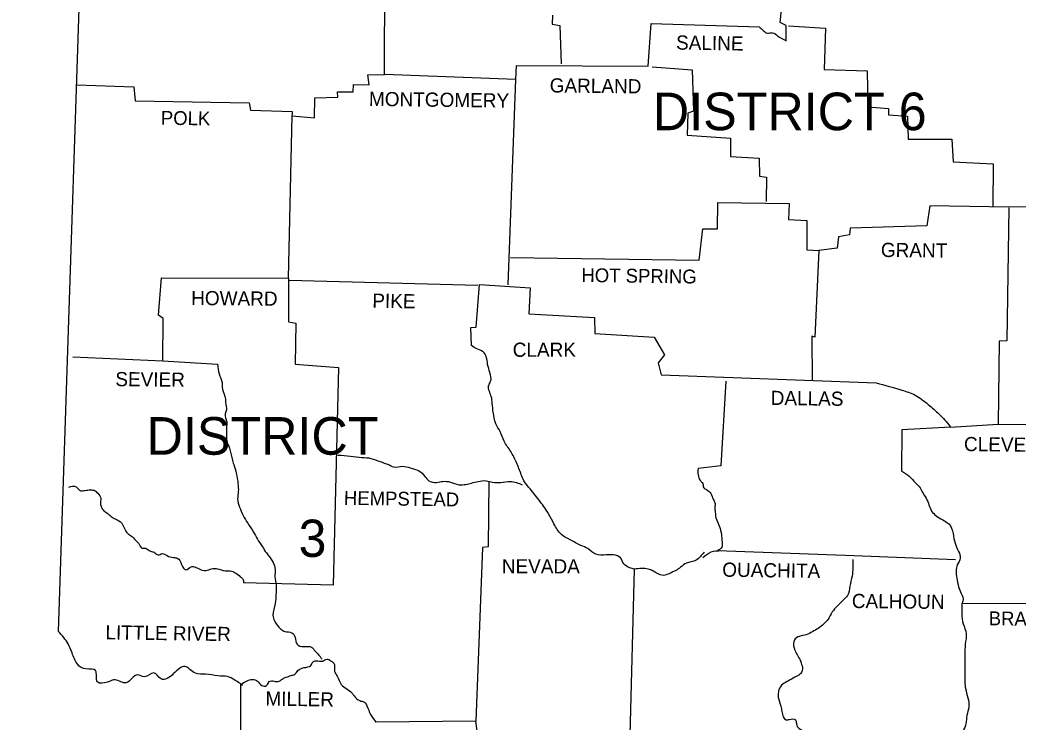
# Model space of a CAD drawing. Extents: x 1373884 to 1377798, y 1168424 to 1170626.
# Drawn here: x 1376295.6 to 1376598.2, y 1169816.4 to 1170029.4 of the extents above; entities that cross this region are included whole.
import ezdxf

# ---------------------------------------------------------------- set-up
doc = ezdxf.new("R2010")
doc.units = 0
doc.layers.add('R_Draft', color=7, linetype='Continuous')

msp = doc.modelspace()

# ---------------------------------------------------------------- linework, layer by layer
at = {"layer": 'R_Draft'}
for points in [[(1376307.29, 1169843.9), (1376316.29, 1170115.2), (1376295.59, 1170281.4)], [(1376311.59, 1169927.2), (1376338.89, 1169926), (1376338.99, 1169938.8), (1376337.59, 1169939.8), (1376338.49, 1169951.2), (1376376.99, 1169951.1), (1376378.09, 1170000.3), (1376384.89, 1169999.7), (1376384.99, 1170005.8), (1376391.99, 1170006), (1376391.89, 1170007.6), (1376396.59, 1170007.6), (1376396.69, 1170009.8), (1376401.49, 1170009.7), (1376401.09, 1170012.7), (1376406.09, 1170012.8), (1376406.29, 1170071.3)], [(1376527.89, 1170023.1), (1376527.89, 1170027.7), (1376526.09, 1170028.6), (1376526.79, 1170035.6), (1376539.09, 1170036.3), (1376539.49, 1170040.2), (1376552.59, 1170040.7), (1376552.29, 1170043.4), (1376559.49, 1170042.6)], [(1376457.09, 1170030.8), (1376456.99, 1170028.1), (1376459.29, 1170027.7), (1376459.69, 1170016.1)], [(1376445.89, 1170011.3), (1376446.09, 1170015.6), (1376486.09, 1170015.4), (1376486.99, 1170028.3), (1376519.69, 1170027.3)], [(1376528.59, 1170027.6), (1376539.79, 1170026.9), (1376539.39, 1170014.4), (1376552.49, 1170013.9), (1376552.69, 1170003), (1376558.89, 1170002.5), (1376558.89, 1170000.6), (1376564.69, 1170000.2), (1376564.89, 1169993.2), (1376578.09, 1169993.2), (1376578.49, 1169986.3), (1376590.69, 1169985.7), (1376590.59, 1169972.7)], [(1376487.29, 1170015.2), (1376499.39, 1170014.3), (1376499.79, 1170001.7), (1376498.09, 1170001.1), (1376497.89, 1169994.4), (1376510.99, 1169993.5), (1376510.99, 1169988), (1376519.69, 1169987.5), (1376519.79, 1169982), (1376521.89, 1169981.7), (1376521.79, 1169974.3)], [(1376445.89, 1170011.3), (1376406.09, 1170012.8)], [(1376443.59, 1169949), (1376445.89, 1170011.3)], [(1376312.79, 1170009.7), (1376330.09, 1170009.1), (1376330.49, 1170004.9), (1376365.09, 1170004.2), (1376365.49, 1170002), (1376378.09, 1170001.6), (1376377.99, 1169999.7)], [(1376709.89, 1169984.2), (1376672.09, 1169985.2), (1376671.89, 1169972.9), (1376595.39, 1169972.6)], [(1376444.29, 1169957.3), (1376501.49, 1169956.5), (1376502.59, 1169966), (1376507.09, 1169966), (1376507.19, 1169974), (1376528.79, 1169973.7), (1376528.59, 1169968.9), (1376534.19, 1169968.5), (1376534.19, 1169959.7), (1376537.79, 1169959.4)], [(1376595.39, 1169972.6), (1376571.49, 1169973), (1376570.59, 1169966.9), (1376547.29, 1169966.2), (1376547.09, 1169964.2), (1376543.79, 1169963.6), (1376543.39, 1169960.2), (1376537.79, 1169959.4)], [(1376595.39, 1169972.4), (1376594.79, 1169932), (1376592.49, 1169931.9), (1376592.19, 1169906.8)], [(1376537.79, 1169959.4), (1376536.59, 1169933.2), (1376535.69, 1169933.5), (1376535.79, 1169919.9)], [(1376376.99, 1169951.1), (1376376.99, 1169937.8), (1376379.19, 1169937.4), (1376378.99, 1169925), (1376392.19, 1169924), (1376390.59, 1169857.9), (1376363.39, 1169858.6)], [(1376377.19, 1169950.4), (1376434.39, 1169948.9)], [(1376432.49, 1169930.6), (1376432.29, 1169936.1), (1376433.89, 1169936.2), (1376434.89, 1169949.1), (1376450.29, 1169948.1), (1376449.89, 1169940.2), (1376469.79, 1169939.1), (1376469.89, 1169934.3), (1376487.89, 1169933.2), (1376490.99, 1169927.8), (1376489.09, 1169925.4), (1376489.99, 1169921.7), (1376555.19, 1169919.3)], [(1376338.89, 1169926), (1376355.49, 1169925)], [(1376509.59, 1169919.8), (1376508.09, 1169894.1), (1376501.19, 1169893.3)], [(1376577.79, 1169905.9), (1376562.99, 1169905), (1376562.89, 1169892.5)], [(1376577.59, 1169905.9), (1376592.19, 1169906.8)], [(1376592.19, 1169906.8), (1376627.59, 1169906.6)], [(1376437.79, 1169889.5), (1376437.59, 1169869.6), (1376435.79, 1169869.4), (1376433.79, 1169816.7)], [(1376507.09, 1169868.4), (1376548.49, 1169866.9), (1376579.19, 1169865.7)], [(1376448.99, 1169810.7), (1376466.99, 1169809.6), (1376467.09, 1169813.3), (1376480.59, 1169812.4), (1376481.89, 1169862.8)], [(1376581.19, 1169852.4), (1376626.39, 1169852.5)], [(1376729.29, 1169746.3), (1376362.79, 1169746.9), (1376362.59, 1169827.8)], [(1376448.99, 1169810.7), (1376434.49, 1169811.5), (1376433.79, 1169816.7), (1376403.49, 1169816.4)]]:
    msp.add_lwpolyline(points, dxfattribs=at)
for points in [[(1376519.69, 1170027.3), (1376520.89, 1170026.2), (1376522.19, 1170025.4), (1376523.79, 1170025.5), (1376525.29, 1170024.6), (1376527.89, 1170023.1)], [(1376481.89, 1169862.8), (1376480.49, 1169863.2), (1376478.69, 1169864.4), (1376477.69, 1169866.2), (1376475.59, 1169867.1), (1376473.29, 1169867.1), (1376470.19, 1169867.3), (1376467.79, 1169869), (1376465.69, 1169870), (1376462.39, 1169871.7), (1376459.79, 1169873.3), (1376457.49, 1169876.5), (1376455.99, 1169879.4), (1376453.29, 1169883.3), (1376450.29, 1169887.1), (1376448.39, 1169889.6), (1376446.89, 1169893.3), (1376446.09, 1169895.1), (1376444.39, 1169898.5), (1376442.39, 1169901.6), (1376441.19, 1169904.5), (1376439.89, 1169906.9), (1376439.09, 1169910.4), (1376438.79, 1169913), (1376438.49, 1169915.2), (1376437.69, 1169918.4), (1376438.29, 1169919.8), (1376438.09, 1169922.4), (1376437.39, 1169924.9), (1376436.99, 1169927.2), (1376435.99, 1169928.7), (1376434.09, 1169929.6), (1376432.49, 1169930.6)], [(1376355.49, 1169925), (1376355.99, 1169922), (1376356.89, 1169919.4), (1376356.99, 1169917.4), (1376357.89, 1169914.4), (1376357.89, 1169913.3), (1376358.19, 1169911.1), (1376357.79, 1169909.9), (1376358.29, 1169907.5), (1376358.19, 1169905.7), (1376358.19, 1169904.2), (1376358.29, 1169901.7), (1376359.09, 1169899.5), (1376359.89, 1169896.2), (1376360.39, 1169894.5), (1376361.19, 1169891.9), (1376361.69, 1169888.7), (1376361.79, 1169886.3), (1376361.59, 1169884.1), (1376362.19, 1169881.6), (1376363.29, 1169879.1), (1376364.69, 1169876.7), (1376366.39, 1169874), (1376367.59, 1169871.9), (1376369.09, 1169869.6), (1376370.29, 1169867.7), (1376372.09, 1169865.3), (1376372.89, 1169863.3), (1376372.89, 1169860.5), (1376373.29, 1169857.9), (1376373.19, 1169855), (1376372.99, 1169852.4), (1376372.29, 1169848.8), (1376372.79, 1169847.1), (1376374.69, 1169844.6), (1376375.89, 1169843.9), (1376377.99, 1169843.5), (1376378.99, 1169842.1), (1376379.59, 1169840), (1376381.69, 1169839.3), (1376383.99, 1169839.1), (1376385.09, 1169837.9), (1376386.59, 1169836.3), (1376387.09, 1169835.5)], [(1376555.19, 1169919.3), (1376562.99, 1169917.1), (1376566.99, 1169915.6), (1376570.99, 1169912.7), (1376574.29, 1169909.8), (1376577.59, 1169906.1)], [(1376391.99, 1169897.4), (1376395.79, 1169897.1), (1376399.29, 1169896.7), (1376401.99, 1169896.4), (1376404.79, 1169895.4), (1376407.29, 1169894.5), (1376408.89, 1169893.8), (1376411.59, 1169894), (1376413.89, 1169893.5), (1376416.49, 1169892.6), (1376418.39, 1169890.9), (1376419.59, 1169889.6), (1376421.89, 1169889.1), (1376423.79, 1169889.4), (1376426.09, 1169889.2), (1376428.69, 1169888.4), (1376430.79, 1169888.5), (1376432.49, 1169888.9), (1376434.49, 1169889.4), (1376436.99, 1169889.6), (1376438.89, 1169889.2), (1376441.39, 1169889.1), (1376444.29, 1169889.4), (1376447.89, 1169888.4)], [(1376501.19, 1169893.3), (1376501.19, 1169891.4), (1376501.89, 1169889.6), (1376502.59, 1169888.8), (1376502.89, 1169887.5), (1376503.79, 1169886.9), (1376505.09, 1169885.7), (1376505.79, 1169884), (1376506.29, 1169882.9), (1376506.29, 1169881.5), (1376506.39, 1169880.1), (1376506.59, 1169878.4), (1376507.79, 1169875.4), (1376508.09, 1169874.2), (1376508.29, 1169873.2), (1376508.39, 1169871.5), (1376508.39, 1169869.5), (1376507.09, 1169868.4)], [(1376562.89, 1169892.5), (1376565.19, 1169891), (1376567.09, 1169889), (1376568.49, 1169887.5), (1376569.39, 1169885.8), (1376570.59, 1169883.8), (1376572.29, 1169880), (1376573.79, 1169878.7), (1376575.89, 1169877.4), (1376577.19, 1169876.5), (1376578.49, 1169873.6), (1376579.09, 1169870.7), (1376580.19, 1169868.1), (1376580.69, 1169866.1), (1376579.79, 1169864.1), (1376579.59, 1169860.1), (1376580.19, 1169857.4), (1376580.99, 1169855.4), (1376581.49, 1169853.1), (1376581.19, 1169852.4)], [(1376310.39, 1169887.7), (1376312.59, 1169887.8), (1376314.09, 1169886.5), (1376314.99, 1169886.6), (1376316.59, 1169886.8), (1376318.09, 1169886.7), (1376319.19, 1169885.8), (1376320.09, 1169884.2), (1376319.99, 1169882.7), (1376320.09, 1169882.1), (1376320.79, 1169880.8), (1376321.99, 1169879.8), (1376323.29, 1169878.8), (1376324.49, 1169878), (1376326.49, 1169876.7), (1376326.69, 1169876.3), (1376327.49, 1169874.7), (1376328.49, 1169873.4), (1376329.69, 1169872.6), (1376330.99, 1169871.2), (1376331.59, 1169870.6), (1376332.59, 1169869.2), (1376333.69, 1169869.1), (1376335.19, 1169868.2), (1376336.29, 1169867.9), (1376337.49, 1169867.1), (1376338.69, 1169867.5), (1376340.19, 1169866.9), (1376342.19, 1169866.3), (1376343.29, 1169866.1), (1376344.59, 1169864.2), (1376345.89, 1169862.6), (1376347.49, 1169863.5), (1376350.49, 1169862.6), (1376352.39, 1169862.5), (1376354.09, 1169863), (1376355.39, 1169862.9), (1376357.79, 1169862.3), (1376359.29, 1169862.3), (1376360.89, 1169861.7), (1376362.39, 1169860.5), (1376363.39, 1169859.2), (1376363.39, 1169858.6)], [(1376502.99, 1169867.9), (1376501.89, 1169866.6), (1376500.59, 1169865.5), (1376499.09, 1169865), (1376497.69, 1169864.6), (1376495.89, 1169863.4), (1376494.49, 1169862.4), (1376492.59, 1169861.5), (1376490.79, 1169860.9), (1376488.59, 1169861.6), (1376487.39, 1169862.3), (1376486.09, 1169862.8), (1376481.89, 1169862.8)], [(1376502.59, 1169866.3), (1376505.19, 1169868), (1376508.09, 1169868.4)], [(1376548.09, 1169865.7), (1376547.89, 1169860.7), (1376547.19, 1169857.6), (1376546.49, 1169854.8), (1376544.99, 1169853.2), (1376543.39, 1169851.6), (1376541.89, 1169849.8), (1376540.59, 1169847.6), (1376539.29, 1169846.2), (1376537.59, 1169844.8), (1376535.89, 1169843.8), (1376533.99, 1169842.9), (1376531.89, 1169842.4), (1376530.39, 1169841.3), (1376530.29, 1169838.9), (1376531.99, 1169835.5), (1376532.59, 1169833.9), (1376532.79, 1169832), (1376532.09, 1169830.9), (1376530.49, 1169830), (1376528.59, 1169828.9), (1376526.89, 1169827.9), (1376525.69, 1169826.2), (1376525.49, 1169823.9), (1376526.29, 1169821.2), (1376526.59, 1169819.6), (1376527.89, 1169817.1), (1376528.89, 1169817.2), (1376530.69, 1169817.1), (1376530.89, 1169816.6), (1376530.99, 1169816.1), (1376531.39, 1169814.8), (1376532.89, 1169813.7), (1376533.09, 1169812.7), (1376533.99, 1169810.8), (1376535.49, 1169809.5), (1376536.59, 1169809.1), (1376538.89, 1169808.4), (1376540.09, 1169808.1), (1376541.39, 1169805.2), (1376542.99, 1169805.3), (1376544.19, 1169805.5), (1376546.19, 1169805), (1376547.09, 1169803.8), (1376547.99, 1169801.8), (1376549.19, 1169800.4), (1376549.99, 1169800.4)], [(1376581.19, 1169852.4), (1376581.59, 1169846.2), (1376582.49, 1169843.2), (1376582.19, 1169840), (1376582.09, 1169836.9), (1376582.09, 1169834.1), (1376582.09, 1169831.4), (1376582.09, 1169828.6), (1376582.29, 1169826.6), (1376582.99, 1169823.7), (1376583.29, 1169821), (1376582.69, 1169818.4), (1376582.39, 1169816), (1376581.59, 1169813.6), (1376580.89, 1169810.9), (1376580.09, 1169807.4), (1376579.39, 1169805.1), (1376577.99, 1169802.7), (1376577.09, 1169800.5), (1376575.69, 1169799.1), (1376575.49, 1169796.7), (1376575.79, 1169794.5), (1376575.59, 1169792.5), (1376576.29, 1169790.6), (1376578.09, 1169789.3)], [(1376362.59, 1169827.8), (1376362.99, 1169827.6), (1376361.09, 1169828.9), (1376358.49, 1169830.2), (1376355.59, 1169830.4), (1376351.89, 1169830.9), (1376348.79, 1169831.2), (1376345.59, 1169833.3), (1376342.19, 1169831.1), (1376338.39, 1169829.5), (1376336.19, 1169831.3), (1376333.29, 1169830.1), (1376331.29, 1169830.7), (1376327.79, 1169828.3), (1376324.49, 1169829.2), (1376322.09, 1169828.5), (1376319.09, 1169828.6), (1376318.49, 1169832), (1376315.59, 1169832.5), (1376313.09, 1169833.9), (1376311.39, 1169837.4), (1376310.19, 1169840.1), (1376307.29, 1169843.9)], [(1376362.59, 1169827.8), (1376366.09, 1169829.3), (1376367.59, 1169828.8), (1376368.89, 1169827.5), (1376370.39, 1169827.5), (1376371.19, 1169828.7), (1376372.69, 1169828.8), (1376373.89, 1169828.7), (1376375.19, 1169829.5), (1376376.29, 1169830), (1376377.79, 1169830.5), (1376378.89, 1169830.9), (1376379.89, 1169832), (1376381.69, 1169832.9), (1376383.79, 1169833.6), (1376384.39, 1169834.6), (1376385.39, 1169835), (1376387.39, 1169834.9), (1376388.69, 1169835.5), (1376389.79, 1169835), (1376390.79, 1169834.3), (1376390.99, 1169831.7), (1376391.79, 1169830.3), (1376392.99, 1169827.8), (1376394.69, 1169826.5), (1376396.29, 1169825.2), (1376396.89, 1169824.4), (1376398.59, 1169822.9), (1376400.09, 1169822.4), (1376400.79, 1169821.3), (1376401.89, 1169818.7), (1376403.49, 1169816.4)]]:
    msp.add_spline(points, degree=3, dxfattribs=at)

# ---------------------------------------------------------------- texts
for s, height, rotation, p in [('SALINE', 4.301, 359.1491, (1376494.49, 1170020.4)), ('GARLAND', 4.301, 359.3658, (1376456.19, 1170007.4)), ('MONTGOMERY', 4.301, 359.2944, (1376401.39, 1170003.3)), ('POLK', 4.199, 359.2152, (1376338.29, 1169997.6)), ('GRANT', 4.301, 359.4032, (1376556.59, 1169957.5)), ('HOT SPRING', 4.201, 359.2216, (1376465.79, 1169949.9)), ('HOWARD', 4.301, 359.5145, (1376347.49, 1169942.9)), ('PIKE', 4.3, 359.0452, (1376402.39, 1169942.1)), ('SEVIER', 4.301, 359.4271, (1376324.49, 1169918.3)), ('DALLAS', 4.3, 359.2462, (1376523.19, 1169912.6)), ('CLEVELAND', 4.301, 359.3376, (1376581.79, 1169898.6)), ('HEMPSTEAD', 4.199, 359.1885, (1376393.79, 1169882.3)), ('OUACHITA', 4.301, 359.2043, (1376508.49, 1169860.5)), ('CALHOUN', 4.301, 359.3634, (1376547.79, 1169851)), ('BRADLEY', 4.199, 359.1449, (1376589.29, 1169845.8)), ('LITTLE RIVER', 4.3008, 359.1697, (1376321.49, 1169841.5)), ('MILLER', 4.3, 359.1319, (1376369.99, 1169821.4))]:
    msp.add_text(s, height=height, rotation=rotation, dxfattribs=at).set_placement(p)
for s, height, p in [('DISTRICT 6', 11.4, (1376487.48, 1169995.94)), ('CLARK', 4.3, (1376444.99, 1169927.2)), ('DISTRICT', 11.4, (1376333.99, 1169897.5)), ('3', 11.3, (1376380.09, 1169866.5)), ('NEVADA', 4.3, (1376441.69, 1169861.5))]:
    msp.add_text(s, height=height, dxfattribs=at).set_placement(p)

doc.saveas('drawing.dxf')
